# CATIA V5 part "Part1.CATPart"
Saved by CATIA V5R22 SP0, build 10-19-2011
Part number: Part1
Bounding box of the stored display mesh (mm): x -87.5 to 89.5, y -87.5 to 89.999, z 0 to 302
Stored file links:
  C:\Users\dussa\Documents\ENIB\S5\inter\Part1.CATPart
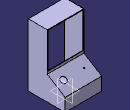
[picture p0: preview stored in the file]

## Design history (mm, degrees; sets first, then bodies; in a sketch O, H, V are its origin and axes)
Body1 (main body)
  Sketch1 on xy-plane, origin (0, 0, 0), H (1, 0, 0), V (0, 1, 0)
    line L1 (-87.5, 87.5) -> (87.5, 87.5)
    line L2 (87.5, 87.5) -> (87.5, -87.5)
    line L3 (87.5, -87.5) -> (-87.5, -87.5)
    line L4 (-87.5, -87.5) -> (-87.5, 87.5)
    distance L1 L3 = 175
    distance L4 L2 = 175
    horizontal: L1 H, L3 H
    vertical: L2 V, L4 V
    symmetry: L3 L1 H, L4 L2 V
  Pad1: profile Sketch1, direction (0, 0, 1), length 2
  Sketch2 on face of Pad1 from Sketch1.L2, origin (87.5, 0, 0), H (0, 1, 0), V (0, 0, 1)
    point P1 (-87.5, 0)
    line L1 (-87.5, 0) -> (87.5, 0)
    line L2 (87.5, 0) -> (87.5, 62.3217)
    line L3 (-87.5, 80) -> (-87.5, 0)
    point P3 (87.5, 62.3217)
    point P4 (-87.5, 80)
    reference projected line E1 (-87.5, 0) -> (-87.5, 2) from edge [face of Pad1 from Sketch1.L2 | face of Pad1 from Sketch1.L3]
    reference projected line E2 (87.5, 0) -> (87.5, 2) from edge [face of Pad1 from Sketch1.L1 | face of Pad1 from Sketch1.L2]
    reference projected line E3 (-87.5, 0) -> (87.5, 0) from edge [start face of Pad1 | face of Pad1 from Sketch1.L2]
    line L4 (-87.5, 300) -> (2.5, 300)
    line L5 (2.5, 300) -> (2.5, 115)
    line L6 (-87.5, 80) -> (-87.5, 300)
    point P8 (-87.5, 80)
    line L7 (2.5, 115) -> (87.5, 62.3217)
    point P9 (87.5, 62.3217)
    distance P4 P1 = 80
    distance L1 L4 = 300
    length L5 = 185
    distance L5 L6 = 90
    length L7 = 100
    horizontal: L1 H, L4 H
    vertical: L2 V, L3 V, L5 V, L6 V
    coincidence: E1 L3, L2 E2, L1 E3, L6 L3, P8 P4, L7 P3, P3 P9
  Pad2: profile Sketch2, direction (1, 0, 0), length 2
  Sketch3 on face of Pad1 from Sketch1.L4, origin (-87.5, 0, 0), H (0, 1, 0), V (0, 0, 1)
    point P1 (-87.5, 0)
    line L1 (-87.5, 0) -> (87.5, 0)
    line L2 (87.5, 0) -> (87.5, 62.3217)
    line L3 (-87.5, 80) -> (-87.5, 0)
    point P3 (87.5, 62.3217)
    point P4 (-87.5, 80)
    reference projected line E1 (-87.5, 0) -> (-87.5, 2) from edge [face of Pad1 from Sketch1.L2 | face of Pad1 from Sketch1.L3]
    reference projected line E2 (87.5, 0) -> (87.5, 2) from edge [face of Pad1 from Sketch1.L1 | face of Pad1 from Sketch1.L2]
    reference projected line E3 (-87.5, 0) -> (87.5, 0) from edge [start face of Pad1 | face of Pad1 from Sketch1.L2]
    line L4 (-87.5, 300) -> (2.5, 300)
    line L5 (2.5, 300) -> (2.5, 115)
    line L6 (-87.5, 80) -> (-87.5, 300)
    point P8 (-87.5, 80)
    line L7 (2.5, 115) -> (87.5, 62.3217)
    point P9 (87.5, 62.3217)
    distance P4 P1 = 80
    distance L1 L4 = 300
    length L5 = 185
    distance L5 L6 = 90
    length L7 = 100
    horizontal: L1 H, L4 H
    vertical: L2 V, L3 V, L5 V, L6 V
    coincidence: E1 L3, L2 E2, L1 E3, L6 L3, P8 P4, L7 P3, P3 P9
  Pad3: profile Sketch3, direction (1, 0, 0), length 2
  Sketch4 on face of Pad3 from Sketch3.L4, origin (0, 0, 300), H (1, 0, 0), V (0, 1, 0)
    line L1 (-87.5, 2.5) -> (89.5, 2.5)
    line L2 (89.5, 2.5) -> (89.5, -87.5)
    line L3 (89.5, -87.5) -> (-87.5, -87.5)
    line L4 (-87.5, -87.5) -> (-87.5, 2.5)
    reference projected line E1 (-87.5, -87.5) -> (87.5, -87.5) from edge [face of Pad3 | end face of Pad1]
    reference projected point E2 (89.5, 2.5) from vertex [face of Pad2 from Sketch2.L5 | face of Pad2 from Sketch2.L4 | end face of Pad2]
    reference projected line E3 (-87.5, 2.5) -> (-87.5, -87.5) from edge [start face of Pad3 | face of Pad3 from Sketch3.L4]
    reference projected line E4 (89.5, 2.5) -> (89.5, -87.5) from edge [face of Pad2 from Sketch2.L4 | end face of Pad2]
    horizontal: L1 H, L3 H
    vertical: L2 V, L4 V
    coincidence: L3 E1, L1 E2, L4 E3, E4 L2
  Pad4: profile Sketch4, direction (0, 0, 1), length 2
  Sketch5 on face of Pad3, origin (0, 87.5, 0), H (-1, 0, 0), V (0, 0, 1)
    line L1 (-89.5, 62.3217) -> (87.5, 62.3217)
    line L2 (87.5, 62.3217) -> (87.5, 0)
    line L3 (87.5, 0) -> (-89.5, 0)
    line L4 (-89.5, 0) -> (-89.5, 62.3217)
    reference projected point E1 (85.5, 62.3217) from vertex [end face of Pad3 | face of Pad3 from Sketch3.L2 | face of Pad3 from Sketch3.L7]
    reference projected line E2 (-87.5, 0) -> (87.5, 0) from edge [face of Pad3 | face of Pad3]
    reference projected line E3 (87.5, 0) -> (87.5, 2) from edge [face of Pad3 | face of Pad3]
    reference projected line E4 (-89.5, 0) -> (-89.5, 62.3217) from edge [face of Pad3 | end face of Pad2]
    horizontal: L1 H, L3 H
    vertical: L2 V, L4 V
    coincidence: E1 L1, E2 L3, L2 E3, E4 L4
  Pad5: profile Sketch5, direction (0, 1, 0), length 2
  Sketch6 on face of Pad2 from Sketch2.L7, origin (0, 52.1868, 84.2069), H (-1, 0, 0), V (0, -0.85, 0.5268)
    line L1 (-89.5, 58.455) -> (87.5, 58.455)
    line L2 (87.5, 58.455) -> (87.5, -43.245)
    line L3 (87.5, -43.245) -> (-89.5, -43.245)
    line L4 (-89.5, -43.245) -> (-89.5, 58.455)
    reference projected line E1 (87.5, -43.245) -> (-89.5, -43.245) from edge [face of Pad5 from Sketch5.L1 | end face of Pad5]
    reference projected line E2 (87.5, -41.545) -> (87.5, 58.455) from edge [face of Pad5 | face of Pad3 from Sketch3.L7]
    reference projected line E3 (87.5, 58.455) -> (85.5, 58.455) from edge [face of Pad3 from Sketch3.L5 | face of Pad3 from Sketch3.L7]
    reference projected line E4 (-89.5, -41.545) -> (-89.5, 58.455) from edge [face of Pad2 from Sketch2.L7 | face of Pad5]
    circle A1 centre (-50, 11.755) radius 14.5
    point P5 (-50, 11.755)
    circle A2 centre (50, 11.755) radius 3.35
    point P6 (50, 11.755)
    radius A1 = 14.5
    radius A2 = 3.35
    distance P5 V = 50
    distance P6 V = 50
    distance P5 L3 = 55
    distance P6 L3 = 55
    horizontal: L1 H, L3 H
    vertical: L2 V, L4 V
    coincidence: L3 E1, L2 E2, E3 L1, L4 E4
  Pad6: profile Sketch6, direction (0, 0.5268, 0.85), length 2
  Sketch7 on face of Pad3 from Sketch3.L5, origin (0, 2.5, 0), H (-1, 0, 0), V (0, 0, 1)
    line L1 (-89.5, 302) -> (87.5, 302)
    line L2 (87.5, 302) -> (87.5, 116.7)
    line L3 (87.5, 116.7) -> (-89.5, 116.7)
    line L4 (-89.5, 116.7) -> (-89.5, 302)
    reference projected line E1 (-89.5, 302) -> (87.5, 302) from edge [face of Pad4 from Sketch4.L1 | end face of Pad4]
    reference projected line E2 (87.5, 116.7) -> (-89.5, 116.7) from edge [face of Pad6 from Sketch6.L1 | end face of Pad6]
    reference projected line E3 (-89.5, 115) -> (-89.5, 300) from edge [face of Pad2 from Sketch2.L5 | face of Pad6]
    reference projected line E4 (87.5, 115) -> (87.5, 300) from edge [face of Pad6 | face of Pad3 from Sketch3.L5]
    line L5 (-86, 298.5) -> (84, 298.5)
    line L6 (84, 298.5) -> (84, 128.5)
    line L7 (84, 128.5) -> (-86, 128.5)
    line L8 (-86, 128.5) -> (-86, 298.5)
    distance L6 L8 = 170
    distance L5 L7 = 170
    distance L5 L1 = 3.5
    distance L8 L4 = 3.5
    horizontal: L1 H, L3 H, L5 H, L7 H
    vertical: L2 V, L4 V, L6 V, L8 V
    coincidence: L1 E1, L3 E2, L4 E3, L2 E4
  Pad7: profile Sketch7, direction (0, 1, 0), length 2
